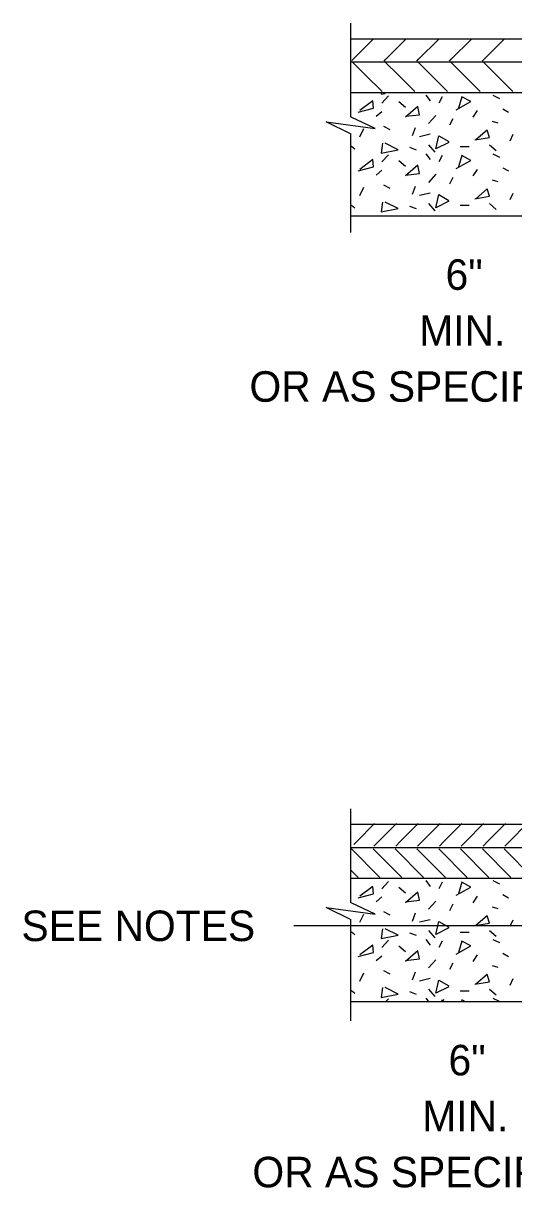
# Model space of a CAD drawing. Extents: x 3.47 to 10.73, y 1.11 to 10.92.
# Drawn here: x 4.894 to 5.858, y 8.502 to 10.791 of the extents above; entities that cross this region are included whole.
import ezdxf

# ---------------------------------------------------------------- set-up
doc = ezdxf.new("R2010")
doc.units = 0
for name, color, linetype in [('DETL-DIMS', 7, 'Continuous'), ('DETL-LINE', 7, 'Continuous'), ('DETL-NOTE', 7, 'Continuous'), ('DETL-PATT', 7, 'Continuous')]:
    doc.layers.add(name, color=color, linetype=linetype)

msp = doc.modelspace()

# ---------------------------------------------------------------- linework, layer by layer
at = {"layer": 'DETL-DIMS'}
msp.add_line((6.0971, 9.0169), (5.4256, 9.0169), dxfattribs=at)
at = {"layer": 'DETL-LINE'}
for p, q in [((5.5382, 10.6066), (5.5382, 10.7911)), ((5.5382, 10.7608), (6.114, 10.7608)), ((5.5382, 10.7153), (6.114, 10.7153)), ((5.5382, 10.6547), (6.2958, 10.6547)), ((5.5382, 10.3797), (5.5382, 10.5732)), ((5.5382, 10.4123), (6.2958, 10.4123)), ((5.5382, 9.0624), (5.5382, 9.2469)), ((5.5382, 9.2166), (8.3867, 9.2166)), ((5.5382, 9.1711), (8.3867, 9.1711)), ((5.5382, 9.1105), (8.3867, 9.1105)), ((5.5382, 8.83), (5.5382, 9.0291)), ((5.5382, 8.8681), (6.2958, 8.8681))]:
    msp.add_line(p, q, dxfattribs=at)
for points in [[(5.5385, 10.5731), (5.4894, 10.5972), (5.5855, 10.5841), (5.5385, 10.6064)], [(5.5385, 9.0289), (5.4894, 9.053), (5.5855, 9.0399), (5.5385, 9.0623)]]:
    msp.add_lwpolyline(points, dxfattribs=at)
at = {"layer": 'DETL-PATT'}
for p, q in [((5.5425, 10.7203), (5.582, 10.7598)), ((5.6068, 10.7203), (5.6462, 10.7598)), ((5.671, 10.7203), (5.7105, 10.7598)), ((5.7353, 10.7203), (5.7748, 10.7598)), ((5.7996, 10.7203), (5.8391, 10.7598)), ((5.5397, 10.7176), (5.5425, 10.7203)), ((5.567, 10.6891), (5.5413, 10.7148)), ((5.6031, 10.7167), (5.6068, 10.7203)), ((5.6313, 10.6891), (5.6056, 10.7148)), ((5.6674, 10.7167), (5.671, 10.7203)), ((5.6956, 10.6891), (5.6699, 10.7148)), ((5.7316, 10.7167), (5.7353, 10.7203)), ((5.7599, 10.6891), (5.7342, 10.7148)), ((5.7959, 10.7167), (5.7996, 10.7203)), ((5.8242, 10.6891), (5.7985, 10.7148)), ((5.5992, 10.657), (5.567, 10.6891)), ((5.6635, 10.657), (5.6313, 10.6891)), ((5.7278, 10.657), (5.6956, 10.6891)), ((5.792, 10.657), (5.7599, 10.6891)), ((5.8563, 10.657), (5.8242, 10.6891)), ((5.5988, 10.6339), (5.6116, 10.6483)), ((5.6854, 10.6499), (5.6935, 10.6387)), ((5.7175, 10.6467), (5.7111, 10.6339)), ((5.817, 10.6499), (5.8298, 10.6435)), ((5.6325, 10.6371), (5.6453, 10.6259)), ((5.8363, 10.6227), (5.8475, 10.6163)), ((5.5875, 10.6082), (5.5988, 10.6179)), ((5.7047, 10.6098), (5.6902, 10.5938)), ((5.7384, 10.6034), (5.732, 10.5906)), ((5.7785, 10.6066), (5.7865, 10.6195)), ((5.8154, 10.5986), (5.8266, 10.5954)), ((5.5555, 10.5681), (5.5635, 10.5842)), ((5.602, 10.589), (5.6148, 10.5826)), ((5.6646, 10.5858), (5.6581, 10.5697)), ((5.6935, 10.5729), (5.6726, 10.5681)), ((5.8507, 10.5601), (5.8571, 10.5729)), ((5.5393, 10.5493), (5.5458, 10.544)), ((5.5988, 10.5184), (5.6116, 10.5328)), ((5.6533, 10.5473), (5.6662, 10.5424)), ((5.6854, 10.5344), (5.6935, 10.5232)), ((5.6902, 10.5521), (5.7031, 10.5376)), ((5.7175, 10.5312), (5.7111, 10.5184)), ((5.7528, 10.5489), (5.7705, 10.5489)), ((5.8106, 10.5521), (5.8234, 10.5408)), ((5.817, 10.5344), (5.8298, 10.528)), ((5.6325, 10.5216), (5.6453, 10.5103)), ((5.8363, 10.5071), (5.8475, 10.5007)), ((5.5875, 10.4927), (5.5988, 10.5023)), ((5.7047, 10.4943), (5.6902, 10.4783)), ((5.7384, 10.4879), (5.732, 10.475)), ((5.7785, 10.4911), (5.7865, 10.5039)), ((5.5555, 10.4526), (5.5635, 10.4686)), ((5.602, 10.4734), (5.6148, 10.467)), ((5.6646, 10.4702), (5.6581, 10.4542)), ((5.8154, 10.4831), (5.8266, 10.4799)), ((5.6935, 10.4574), (5.6726, 10.4526)), ((5.8507, 10.4446), (5.8571, 10.4574)), ((5.5393, 10.4337), (5.5458, 10.4285)), ((5.6533, 10.4317), (5.6662, 10.4269)), ((5.6902, 10.4365), (5.7031, 10.4221)), ((5.7528, 10.4333), (5.7705, 10.4333)), ((5.8106, 10.4365), (5.8234, 10.4253)), ((5.5494, 9.1826), (5.5847, 9.2179)), ((5.5923, 9.1826), (5.6275, 9.2179)), ((5.6351, 9.1826), (5.6704, 9.2179)), ((5.678, 9.1826), (5.7132, 9.2179)), ((5.7208, 9.1826), (5.7561, 9.2179)), ((5.7637, 9.1826), (5.7989, 9.2179)), ((5.8065, 9.1826), (5.8418, 9.2179)), ((5.8494, 9.1826), (5.8846, 9.2179)), ((5.5435, 9.1768), (5.5494, 9.1826)), ((5.5834, 9.1738), (5.5923, 9.1826)), ((5.6263, 9.1738), (5.6351, 9.1826)), ((5.6692, 9.1738), (5.678, 9.1826)), ((5.712, 9.1738), (5.7208, 9.1826)), ((5.7549, 9.1738), (5.7637, 9.1826)), ((5.7977, 9.1738), (5.8065, 9.1826)), ((5.8406, 9.1738), (5.8494, 9.1826)), ((5.595, 9.1121), (5.5392, 9.168)), ((5.6379, 9.1121), (5.5821, 9.168)), ((5.6808, 9.1121), (5.6249, 9.168)), ((5.7236, 9.1121), (5.6678, 9.168)), ((5.7665, 9.1121), (5.7106, 9.168)), ((5.8093, 9.1121), (5.7535, 9.168)), ((5.8522, 9.1121), (5.7964, 9.168)), ((5.895, 9.1121), (5.8392, 9.168)), ((5.5522, 9.1121), (5.5382, 9.1261)), ((5.5988, 9.0897), (5.6116, 9.1042)), ((5.6325, 9.0929), (5.6453, 9.0817)), ((5.6854, 9.1058), (5.6935, 9.0945)), ((5.7175, 9.1026), (5.7111, 9.0897)), ((5.817, 9.1058), (5.8298, 9.0993)), ((5.5875, 9.064), (5.5988, 9.0737)), ((5.7047, 9.0656), (5.6902, 9.0496)), ((5.7785, 9.0624), (5.7865, 9.0753)), ((5.8363, 9.0785), (5.8475, 9.0721)), ((5.602, 9.0448), (5.6148, 9.0384)), ((5.6646, 9.0416), (5.6581, 9.0255)), ((5.7384, 9.0592), (5.732, 9.0464)), ((5.8154, 9.0544), (5.8266, 9.0512)), ((5.5555, 9.0239), (5.5635, 9.04)), ((5.6935, 9.0287), (5.6726, 9.0239)), ((5.8507, 9.0159), (5.8571, 9.0287)), ((5.5393, 9.0051), (5.5458, 8.9999)), ((5.6533, 9.0031), (5.6662, 8.9983)), ((5.6902, 9.0079), (5.7031, 8.9934)), ((5.7528, 9.0047), (5.7705, 9.0047)), ((5.8106, 9.0079), (5.8234, 8.9967)), ((5.5988, 8.9742), (5.6116, 8.9886)), ((5.6325, 8.9774), (5.6453, 8.9662)), ((5.6854, 8.9902), (5.6935, 8.979)), ((5.7175, 8.987), (5.7111, 8.9742)), ((5.817, 8.9902), (5.8298, 8.9838)), ((5.5875, 8.9485), (5.5988, 8.9581)), ((5.7047, 8.9501), (5.6902, 8.9341)), ((5.7785, 8.9469), (5.7865, 8.9597)), ((5.8363, 8.963), (5.8475, 8.9565)), ((5.602, 8.9293), (5.6148, 8.9228)), ((5.7384, 8.9437), (5.732, 8.9309)), ((5.8154, 8.9389), (5.8266, 8.9357)), ((5.5555, 8.9084), (5.5635, 8.9244)), ((5.6646, 8.926), (5.6581, 8.91)), ((5.6935, 8.9132), (5.6726, 8.9084)), ((5.8507, 8.9004), (5.8571, 8.9132)), ((5.5393, 8.8896), (5.5458, 8.8843)), ((5.6533, 8.8875), (5.6662, 8.8827)), ((5.6902, 8.8924), (5.7031, 8.8779)), ((5.7528, 8.8891), (5.7705, 8.8891)), ((5.8106, 8.8924), (5.8234, 8.8811)), ((5.6076, 8.8686), (5.6116, 8.8731)), ((5.6854, 8.8747), (5.6898, 8.8686)), ((5.7175, 8.8715), (5.7161, 8.8686)), ((5.7178, 8.8681), (5.7216, 8.872)), ((5.817, 8.8747), (5.8292, 8.8686))]:
    msp.add_line(p, q, dxfattribs=at)
for points in [[(5.5974, 10.6531), (5.5972, 10.6516), (5.6056, 10.6531)], [(5.7448, 10.6211), (5.7737, 10.6371), (5.756, 10.6467), (5.7496, 10.6243)], [(5.5522, 10.6163), (5.5827, 10.6243), (5.5811, 10.6387), (5.5555, 10.6195)], [(5.6453, 10.6082), (5.6726, 10.6114), (5.6694, 10.6275), (5.6453, 10.6066)], [(5.7817, 10.5617), (5.8106, 10.5665), (5.8058, 10.5809), (5.7833, 10.5617)], [(5.6004, 10.5553), (5.5972, 10.536), (5.6309, 10.5424), (5.6052, 10.5553)], [(5.7304, 10.5569), (5.7047, 10.544), (5.7111, 10.5697), (5.7304, 10.5585)], [(5.7448, 10.5055), (5.7737, 10.5216), (5.756, 10.5312), (5.7496, 10.5087)], [(5.5522, 10.5007), (5.5827, 10.5087), (5.5811, 10.5232), (5.5555, 10.5039)], [(5.6453, 10.4927), (5.6726, 10.4959), (5.6694, 10.512), (5.6453, 10.4911)], [(5.7817, 10.4462), (5.8106, 10.451), (5.8058, 10.4654), (5.7833, 10.4462)], [(5.6004, 10.4397), (5.5972, 10.4205), (5.6309, 10.4269), (5.6052, 10.4397)], [(5.7304, 10.4413), (5.7047, 10.4285), (5.7111, 10.4542), (5.7304, 10.443)], [(5.5522, 9.0721), (5.5827, 9.0801), (5.5811, 9.0945), (5.5555, 9.0753)], [(5.7448, 9.0769), (5.7737, 9.0929), (5.756, 9.1026), (5.7496, 9.0801)], [(5.6453, 9.064), (5.6726, 9.0673), (5.6694, 9.0833), (5.6453, 9.0624)], [(5.7304, 9.0127), (5.7047, 8.9999), (5.7111, 9.0255), (5.7304, 9.0143)], [(5.7817, 9.0175), (5.8106, 9.0223), (5.8058, 9.0368), (5.7833, 9.0175)], [(5.6004, 9.0111), (5.5972, 8.9918), (5.6309, 8.9983), (5.6052, 9.0111)], [(5.5522, 8.9565), (5.5827, 8.9646), (5.5811, 8.979), (5.5555, 8.9597)], [(5.7448, 8.9614), (5.7737, 8.9774), (5.756, 8.987), (5.7496, 8.9646)], [(5.6453, 8.9485), (5.6726, 8.9517), (5.6694, 8.9678), (5.6453, 8.9469)], [(5.7304, 8.8972), (5.7047, 8.8843), (5.7111, 8.91), (5.7304, 8.8988)], [(5.7817, 8.902), (5.8106, 8.9068), (5.8058, 8.9212), (5.7833, 8.902)], [(5.6004, 8.8956), (5.5972, 8.8763), (5.6309, 8.8827), (5.6052, 8.8956)], [(5.7614, 8.8686), (5.756, 8.8715), (5.7552, 8.8686)]]:
    msp.add_lwpolyline(points, dxfattribs=at)

# ---------------------------------------------------------------- texts
at = {"layer": 'DETL-NOTE'}
for s, p in [('6" ', (5.724, 10.2671)), ('MIN.', (5.6722, 10.1571)), ('OR AS SPECIFIED', (5.3387, 10.0471)), ('SEE NOTES', (4.8907, 8.9869)), ('6" ', (5.7298, 8.7229)), ('MIN.', (5.6781, 8.6129)), ('OR AS SPECIFIED', (5.3445, 8.5029))]:
    msp.add_text(s, height=0.06, dxfattribs=at).set_placement(p)

doc.saveas('drawing.dxf')
